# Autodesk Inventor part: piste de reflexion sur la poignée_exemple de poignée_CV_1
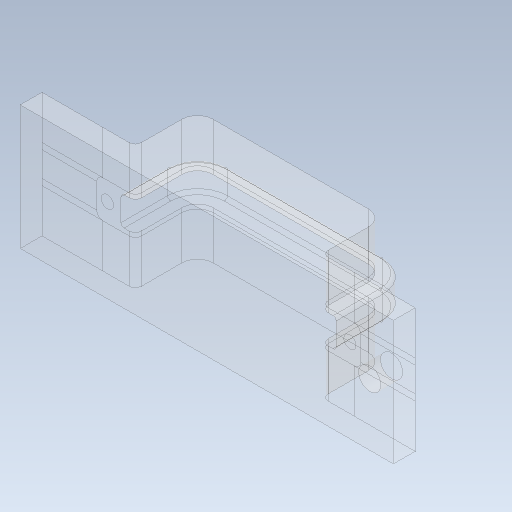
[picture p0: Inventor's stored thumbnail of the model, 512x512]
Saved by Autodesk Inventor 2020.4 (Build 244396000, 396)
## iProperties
Created: 2021-10
Part Number: piste de reflexion sur la poignée_exemple de poignée_CV_1
Material: Générique
Document SubType Name: Modeling
Designer: mel
Density: 1 g/cm^3
Appearance: Par défaut
Author: mel
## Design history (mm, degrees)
node "piste de reflexion sur la poignée_exemple de poignée_CV_Base"
feature "Sculpter2"
feature "Solide1::piste de reflexion sur la poignée_exemple de poigné"
tag "FonctionRepérage1"
node "Solide1"
feature "piste de reflexion sur la poignée_exemple de poignée_CV_Base"
feature "Surface2"
body "Srf2"
